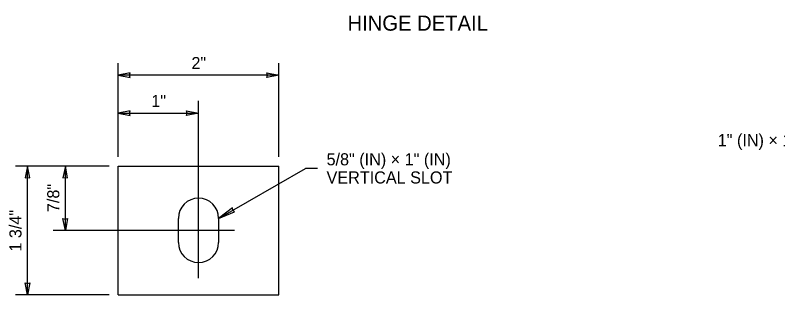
# Model space of a CAD drawing. Extents: x 99862 to 112891, y 95370 to 105076.
# Drawn here: x 101332 to 102341, y 104088 to 104458 of the extents above; entities that cross this region are included whole.
import ezdxf

# ---------------------------------------------------------------- set-up
doc = ezdxf.new("R2010")
doc.units = 0
for name, color, linetype in [('Level 11', 7, 'Continuous'), ('Level 15', 7, 'Continuous'), ('Level 20', 7, 'Continuous')]:
    doc.layers.add(name, color=color, linetype=linetype)

msp = doc.modelspace()

# ---------------------------------------------------------------- linework, layer by layer
at = {"layer": 'Level 11'}
for p, q in [((101468.5, 104088.5), (101468.5, 104258.5)), ((101468.5, 104258.5), (101681, 104258.5)), ((101681, 104088.5), (101681, 104258.5)), ((101548.1, 104157.6), (101548.1, 104189.4)), ((101601.3, 104189.4), (101601.3, 104157.6)), ((101468.5, 104088.5), (101681, 104088.5))]:
    msp.add_line(p, q, dxfattribs=at)
for centre, start, end in [((101574.7, 104189.4), 0, 180), ((101574.7, 104157.6), 180, 0)]:
    msp.add_arc(centre, 26.6, start, end, dxfattribs=at)
at = {"layer": 'Level 15'}
for p, q in [((101468.5, 104270.5), (101468.5, 104394.5)), ((101681, 104270.5), (101681, 104394.5)), ((101681, 104378.5), (101468.5, 104378.5)), ((101468.5, 104328.5), (101574.7, 104328.5)), ((101456.5, 104258.5), (101332.5, 104258.5)), ((101348.5, 104088.5), (101348.5, 104258.5)), ((101398.5, 104173.5), (101398.5, 104258.5)), ((101601.3, 104189.1), (101716.1, 104255.4)), ((101732.1, 104255.4), (101716.1, 104255.4)), ((101622.3, 104173.5), (101382.5, 104173.5)), ((101456.5, 104088.5), (101332.5, 104088.5))]:
    msp.add_line(p, q, dxfattribs=at)
for points in [[(101468.5, 104378.5), (101484.2, 104375.4), (101483.4, 104378.5), (101484.2, 104381.6)], [(101681, 104378.5), (101665.2, 104375.4), (101666, 104378.5), (101665.2, 104381.6)], [(101468.5, 104328.5), (101484.2, 104325.4), (101483.4, 104328.5), (101484.2, 104331.6)], [(101574.7, 104328.5), (101559, 104325.4), (101559.7, 104328.5), (101559, 104331.6)], [(101348.5, 104258.5), (101345.4, 104242.8), (101348.5, 104243.5), (101351.5, 104242.8)], [(101398.5, 104258.5), (101395.4, 104242.8), (101398.5, 104243.5), (101401.5, 104242.8)], [(101601.3, 104189.1), (101622.5, 104197.9), (101620.1, 104200), (101619.5, 104203.1)], [(101398.5, 104173.5), (101395.4, 104189.2), (101398.5, 104188.5), (101401.5, 104189.2)], [(101348.5, 104088.5), (101345.4, 104104.2), (101348.5, 104103.5), (101351.5, 104104.2)]]:
    msp.add_lwpolyline(points, close=True, dxfattribs=at)
msp.add_lwpolyline([(101574.7, 104110.5), (101574.7, 104344.5)], dxfattribs=at)

# ---------------------------------------------------------------- texts
at = {"layer": 'Level 20'}
for s, height, p in [('HINGE DETAIL', 20, (101771.8, 104437.3)), ('2"', 16, (101565.3, 104386.5)), ('1"', 16, (101512.2, 104336.5)), ('5/8" (IN) × 1" (IN)', 16, (101744.1, 104259.4)), ('VERTICAL SLOT', 16, (101744.1, 104235.4))]:
    msp.add_text(s, height=height, dxfattribs=at).set_placement(p)
for s, rotation, p in [('1" (IN) × 1" (IN) × 1/4" (IN) (TYP.)', 360, (102261.6, 104284.7)), ('7/8"', 90, (101390.5, 104197.6)), ('1 3/4"', 90, (101340.5, 104145.4))]:
    msp.add_text(s, height=16, rotation=rotation, dxfattribs=at).set_placement(p)

doc.saveas('drawing.dxf')
